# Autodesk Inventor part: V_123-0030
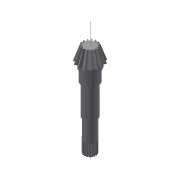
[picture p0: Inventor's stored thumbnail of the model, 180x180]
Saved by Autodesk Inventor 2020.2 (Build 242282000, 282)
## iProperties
+MSCProtocol1+ProtocolID: P00060228091620421
+MSCProtocol2+Protocol: P00060228091620421<@PID>[Version]<@EL>Version=2.2<@EL>[CalcData]<@EL>CalcResult=False<@EL>IsMCW=1<@EL>[Synchronize]<@EL>ChangedVars=<@EL>[Calc]<@EL>Optim=1<@EL>
Manager: www.cadconsulting.pl
Company: Fabian Stasiak CAD Consulting
Shininess: 20.0
Length Units: 11269
Angle Units: 11279
Time Units: 11290
Mass Units: 11283
Length Display Precision: 3
Angle Display Precision: 2
Created: 2001-01
Part Number: V_123-0030
Material: Stal 60
Document SubType Name: Modeling
Description: Koło zęb. stożkowe z=15
Project: Przekładnia X51
Designer: F.Stasiak
Density: 7.85 g/cm^3
Appearance: Stal metaliczna (nierdzewna, szczotkowana)
Density: 7.86
Volumn: 5.864026952018771
Area: 31.42094824814569
PropertySet Name: Model Information
Control State: 0
Master: False
Checked Out: False
TAB_mte: 3
TAB_z1: 15
TAB_z2: 51
TAB_betam: 20
TAB_x: 0.1632
TAB_xt: 0
TAB_delta1: 16.3895
TAB_delta2: 73.6105
TAB_IT: 6e26
TAB_fpt1: ±0.01
TAB_fpt2: ±0.011
TAB_tfa: 0
TAB_sk1: 4.305
TAB_sk2: 3.699
TAB_ECs1: -0.03
TAB_ECd1: -0.08
TAB_ECs2: -0.04
TAB_ECd2: -0.1
TAB_hk1: 2.706
TAB_hk2: 1.837
TAB_omega: 90
TAB_de1: 45
TAB_de2: 153
TAB_le: 79.74
TAB_deltaf1: 14.1558
TAB_deltaf2: 70.6745
TAB_alfat: 20
+MSCFeatProtocols1+FeatNameP00060309103952671: SPLINE2A1
+MSCFeatProtocols2+ProtocolIDP00060309103952671: P00060309103952671
+MSCFeatProtocols3+ProtocolP00060309103952671: P00060309103952671<@PID>[Version]<@EL>Version=2.2<@EL>[Files]<@EL>DataFile=SpiData|Evol<@EL>[Synchronize]<@EL>ChangedVars=<@EL>[Calc]<@EL>CalcName=SPLINE2<@EL>O
Author: F.Stasiak
Subject: Zbiór ćwiczeń. Autodesk Inventor 2020. Kurs podstawowy
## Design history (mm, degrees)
sketch "Base Body Sketch"
  geometry: L1 (15.54, 1.12)-(11.733, 0); L2 (15.54, 1.12)-(25.848, -28.995); L3 (25.848, -28.995)-(19.516, -30.858); L4 (-2.585, 0)-(33.602, 0) reference; L5 (11.733, 0)-(0, 0); L6 (0, -30.858)-(19.516, -30.858); L7 (0, 0)-(0, -30.858); L8 (15.54, 1.12)-(0, 46.52); L9 (0, 0)-(0, 46.52); L10 (0, -38.596)-(0, 69.733) reference; L11 (0, 46.52)-(22.5, -29.98); L12 (0, 46.52)-(11.733, 0); L13 (11.733, 0)-(19.516, -30.858)
  constraints: 22 end point, 3 collinear, 2 parallel, 2 perpendicular, 2 point on line
  dimensions: "d33" = 31.8 distance between parallel lines of L3 L1 (= prf_b); "d34" = 51.696 diameter of L2.end L7 (= msp_dae); "d35" = 39.032 diameter of L3.end L7 (= msp_dfe); "d37" = 79.74 distance from line of L3 L8.end (= prf_le); "d41" = 16.3895 deg angle of L9 L11 (= msp_delta); "d59" = 11.7331 distance of L5.end L1.end (derived)
revolve "Base Body" sketch "Base Body Sketch" stored, may be unused: angle "d10" = 360 deg
node "Tooth Plane"
workpoint "Work Point"
sketch "Sketch2"
  geometry: L1 (5.15, 4.81)-(-5.15, 4.81); L2 (0, -5.75)-(5.15, 4.81); L3 (-5.15, 4.81)-(0, -5.75); L4 (0, 2.5)-(0, -3) reference; L5 (0, 2.5)-(0, -3) reference; L6 (0, 2.5)-(0, -3) reference; L7 (0, -51.448)-(0, 23.35) reference; L8 (0, -51.448)-(0, 23.35) reference; L9 (31.018, -13.126)-(-41.357, -13.126) reference; A1 r 6.536 centre (0, 0.786) between (-5.15, 4.81) and (0, -5.75); 1 further point; 1 other entity
  constraints: 6 end point, 3 point on circle, 2 point on line, 1 centre point, 1 horizontal, 1 vertical alignment, 1 other
  dimensions: "d42" = 52 deg angle of L3 L2 (= msp_a2); "d43" = 10.56 distance from line of L2.start L1 (= 1.6 x msp_he); "d54" = 15.55768 distance of L2.start point (0, -21.308) (= msp_y)
extrude "Tooth" cut sketch "Sketch2" distance "d18" = 32.436 (= 1.02 x prf_b); taper "d19" = -1.88111 deg (= msp_a1)
pattern_circular "Tooth Pattern" dims angle "d22" = 360 deg
revolve "Fix Body" stored, may be unused: angle "d23" = 360 deg
node "Gear Axis"
node "Intersection"
node "Mesh Plane"
sketch "Szkic9"
  geometry: A1 r 19.516 centre (0, 0) between (9.079, 17.275) and (6.763, 18.307) reference; A2 r 19.516 centre (0, 0) between (6.763, 18.307) and (1.268, 19.475) reference; A3 r 19.516 centre (0, 0) between (1.268, 19.475) and (-1.268, 19.475) reference; A4 r 19.516 centre (0, 0) between (-1.268, 19.475) and (-6.763, 18.307) reference; A5 r 19.516 centre (0, 0) between (-6.763, 18.307) and (-9.079, 17.275) reference; A6 r 19.516 centre (0, 0) between (-9.079, 17.275) and (-13.624, 13.973) reference; A7 r 19.516 centre (0, 0) between (-13.624, 13.973) and (-15.321, 12.089) reference; A8 r 19.516 centre (0, 0) between (-15.321, 12.089) and (-18.13, 7.224) reference; A9 r 19.516 centre (0, 0) between (-18.13, 7.224) and (-18.913, 4.812) reference; A10 r 19.516 centre (0, 0) between (-18.913, 4.812) and (-19.501, -0.775) reference; A11 r 19.516 centre (0, 0) between (-19.501, -0.775) and (-19.236, -3.297) reference; A12 r 19.516 centre (0, 0) between (-19.236, -3.297) and (-17.5, -8.639) reference; A13 r 19.516 centre (0, 0) between (-17.5, -8.639) and (-16.232, -10.835) reference; A14 r 19.516 centre (0, 0) between (-16.232, -10.835) and (-12.473, -15.01) reference; A15 r 19.516 centre (0, 0) between (-12.473, -15.01) and (-10.421, -16.501) reference; A16 r 19.516 centre (0, 0) between (-10.421, -16.501) and (-5.289, -18.786) reference; A17 r 19.516 centre (0, 0) between (-5.289, -18.786) and (-2.809, -19.313) reference; A18 r 19.516 centre (0, 0) between (-2.809, -19.313) and (2.809, -19.313) reference; A19 r 19.516 centre (0, 0) between (2.809, -19.313) and (5.289, -18.786) reference; A20 r 19.516 centre (0, 0) between (5.289, -18.786) and (10.421, -16.501) reference; A21 r 19.516 centre (0, 0) between (10.421, -16.501) and (12.473, -15.01) reference; A22 r 19.516 centre (0, 0) between (12.473, -15.01) and (16.232, -10.835) reference; A23 r 19.516 centre (0, 0) between (16.232, -10.835) and (17.5, -8.639) reference; A24 r 19.516 centre (0, 0) between (17.5, -8.639) and (19.236, -3.297) reference; A25 r 19.516 centre (0, 0) between (19.236, -3.297) and (19.501, -0.775) reference; A26 r 19.516 centre (0, 0) between (19.501, -0.775) and (18.913, 4.812) reference; A27 r 19.516 centre (0, 0) between (18.913, 4.812) and (18.13, 7.224) reference; A28 r 19.516 centre (0, 0) between (18.13, 7.224) and (15.321, 12.089) reference; A29 r 19.516 centre (0, 0) between (15.321, 12.089) and (13.624, 13.973) reference; A30 r 19.516 centre (0, 0) between (13.624, 13.973) and (9.079, 17.275) reference
extrude "Wyciągnięcie proste2" join sketch "Szkic9" distance "d77" = 10; taper "d78" = 0 deg
sketch "Szkic10"
  geometry: L1 (19.516, -40.858)-(-19.516, -40.858) reference; L2 (0, -214.658)-(0, 6.542) reference; L3 (-17.5, -40.858)-(-17.5, -65.858); L4 (-17.5, -65.858)-(-14.5, -65.858); L5 (-12.5, -198.858)-(0, -198.858); L6 (0, -40.858)-(-17.5, -40.858); L7 (0, -198.858)-(0, -40.858); L8 (-14.5, -65.858)-(-14.5, -130.858); L9 (-14.5, -130.858)-(-12.5, -130.858); L10 (-12.5, -130.858)-(-12.5, -198.858)
  constraints: 16 end point, 3 parallel, 3 perpendicular, 3 point on line, 2 collinear, 1 midpoint
  dimensions: "d79" = 25 distance of L3.start L3.end; "d83" = 25 diameter of L10 L2; "d84" = 35 diameter of L3 L2; "d85" = 29 diameter of L8 L2; "d86" = 158 distance between parallel lines of L6 L5; "d88" = 68 distance of L9.end L5.start
revolve "Obrót4" sketch "Szkic10" stored, may be unused: angle "d87" = 90 deg
node "Oś konstrukcyjna7"
node "Punkt konstrukcyjny4"
sketch "Szkic11"
  geometry: L1 (0, 0.051)-(0, 12.54); L2 (0, 0.051)-(1.932, 11.007); A1 r 4.835 centre (-3.042, 9.298) between (1.452, 11.081) and (0.545, 12.54); A2 r 11.125 centre (0, 0.051) between (1.452, 11.081) and (1.932, 11.007); A3 r 11.125 centre (0, 0.051) between (1.932, 11.007) and (1.452, 11.081); A4 r 12.5 centre (0, 0.051) between (2.171, 12.362) and (0.545, 12.54); A5 r 11.125 centre (0, 0.051) between (2.408, 10.913) and (1.932, 11.007); A6 r 4.835 centre (6.021, 7.7) between (3.759, 11.973) and (2.408, 10.913); A7 r 12.5 centre (0, 0.051) between (3.759, 11.973) and (2.171, 12.362); 1 further point
  constraints: 14 point on circle, 7 centre point, 5 coincident, 5 end point, 3 symmetric about line, 1 horizontal alignment, 1 point on line, 1 vertical, 3 other
  dimensions: "d89" = 4.83467 radius of A1 (= d90); "d115" = 22.25 diameter of A2 (= d101); "d114" = 3.04162 distance from line of A1.centre L1 (= d111); "d113" = 9.24642 vertical distance of L1.start A1.centre (= d91); "d116" = 10 deg angle of L2 L1 (computed from d96); "d117" = 25 diameter of A4 (= d99)
feature "SPLINE2A1" sketch "Szkic11"
node "Bryła1"
node "Korpusy bryłowe"
node "Korpusy powierzchniowe"
sketch "Sketch7"
  geometry: L1 (-12, 0)-(16, 0) reference; L2 (0, -12)-(0, 16) reference; 2 further points
  constraints: 1 coincident
hole "Hole" sketch "Sketch7" diameter "d47" = 9.758 (= hole); stored, may be unused: countersink angle "d51" = 60 deg, drill point angle "d53" = 118 deg; dims "d48" = 6, "d49" = 4, "d50" = 2, "d52" = 8
sketch "Sketch3"
  geometry: L1 (-11.733, 0)-(0, 0); L2 (-19.516, -30.858)-(-11.733, 0); L3 (0, -30.858)-(-19.516, -30.858); L4 (0, 0)-(0, -30.858); L5 (-19.516, -30.858)-(19.516, -30.858) reference; L6 (-11.733, 0)-(11.733, 0) reference; L7 (0, -33.944)-(0, 9.257) reference; 1 further point
  constraints: 8 end point, 2 horizontal, 2 point on line, 1 vertical
  dimensions: "d57" = 39.032 diameter of L2.start L7 (= msp_dfe); "d58" = 0 distance between parallel lines of L7 L4; "d60" = 11.7331 distance of L1.start L1.end (= d59)
node "Pętla rzutowana2"
other parameters: "prf_le" = 79.74 [user parameter; used in 3 equation terms], "prf_delta1" = 2.86051 [user parameter; used in 1 equation term], "prf_he1" = 6.6 [user parameter; used in 1 equation term], "prf_dfe1" = 39.032 [user parameter; used in 1 equation term], "prf_dae1" = 51.696 [user parameter; used in 1 equation term], "prf_de1" = 45 [user parameter; used in 1 equation term], "prf_b" = 31.8 [user parameter; used in 2 equation terms], "prf_omega" = 90 deg [user parameter; used in 1 equation term], "msp_delta" = 16.3895 deg (= prf_delta1) [user parameter; used in 3 equation terms], "msp_he" = 6.6 (= prf_he1) [user parameter; used in 2 equation terms], "msp_dfe" = 39.032 (= prf_dfe1) [user parameter; used in 3 equation terms], "msp_dae" = 51.696 (= prf_dae1) [user parameter; used in 2 equation terms], "msp_de" = 45 (= prf_de1) [user parameter; used in 1 equation term], "hole" = 9.758 (= 0.25 x msp_dfe) [user parameter; used in 1 equation term], "msp_y" = 15.55768 (computed from msp_delta, msp_dae, msp_he) [user parameter; used in 1 equation term], "msp_a1" = -1.88111 deg (computed from msp_de, msp_z, prf_le) [user parameter; used in 1 equation term], "msp_a2" = 52 deg (computed from msp_z) [user parameter; used in 1 equation term], "msp_dist" = 76.49982 (computed from prf_le, msp_delta) [user parameter], "d0" = 3.62545 (derived), "d4" = 38.7702 (derived), "d6" = 32.175 (derived), "d8" = 21.89 (derived), "d12" = 0 (derived), "d14" = -13.24579 (derived), "d16" = 9.83731 (derived), "d40" = 19.14 (derived), "d62" = 0, "d63" = 90 deg (= prf_omega), "d64" = 2.94118 (computed from prf_z1, prf_z2), "d65" = 0, "d66" = 0, "d90" = 4.83467 (computed from d112, d111, d91) [user parameter; used in 1 equation term], "d91" = 9.24642 (computed from d110, d109, d92) [user parameter; used in 4 equation terms], "d92" = 6.44 (computed from d107, d106, d104, d93) [user parameter; used in 1 equation term], "d93" = -19.56689 (computed from d105, d104, d94) [user parameter; used in 2 equation terms], "d94" = -0.41592 (= d103 - d95) [user parameter; used in 2 equation terms], "d95" = -1.03618 (computed from d98, d96) [user parameter; used in 5 equation terms], "d98" = 11.88889 (= 0.222222 x d101 + 0.277778 x d99) [user parameter; used in 2 equation terms], "d99" = 25 [user parameter; used in 5 equation terms], "d101" = 22.25 [user parameter; used in 5 equation terms], "d103" = -1.4521 (computed from d101, d96) [user parameter; used in 2 equation terms], "d104" = 11.84365 (computed from d98, d96) [user parameter; used in 5 equation terms], "d105" = 11.02982 (computed from d101, d96) [user parameter; used in 2 equation terms], "d106" = 12.4881 (computed from d99, d96) [user parameter; used in 2 equation terms], "d107" = -0.49094 (= d95 - d108) [user parameter; used in 2 equation terms], "d108" = -0.54524 (computed from d99, d96) [user parameter; used in 2 equation terms], "d109" = 21.13399 (computed from d105, d103, d95, d104, d94) [user parameter; used in 2 equation terms], "d110" = 15.17929 (computed from d104, d95, d108, d106, d107) [user parameter; used in 1 equation term], "d111" = 3.04162 (computed from d109, d91, d93) [user parameter; used in 3 equation terms], "d112" = 7.13737 (computed from d95, d111, d104, d91) [user parameter; used in 1 equation term]
